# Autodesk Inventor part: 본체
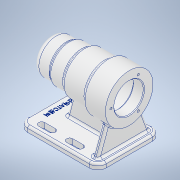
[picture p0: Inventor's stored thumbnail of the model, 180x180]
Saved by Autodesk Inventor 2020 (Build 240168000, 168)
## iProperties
Created: 2021-10
Part Number: 본체
Material: 알루미늄 6061
Document SubType Name: Modeling
Designer: user
Density: 2.7 g/cm^3
Appearance: 알루미늄 - 평지
Mass: 691.322 g
Surface Area: 698.567 cm^2
Volume: 256.045 cm^3
Author: user
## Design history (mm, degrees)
sketch "스케치1"
  geometry: L1 (0, 0)-(0, 27.861); L2 (0, 0)-(112, 0); L3 (112, 0)-(112, 34); L4 (112, 34)-(80, 34); L5 (80, 34)-(80, 30); L6 (80, 30)-(46, 30); L7 (46, 30)-(46, 27); L8 (46, 27)-(24, 27); L9 (24, 27)-(24, 25); L10 (24, 25)-(0, 25); L11 (0, 25)-(0, 0); 1 further point
  constraints: 22 end point, 8 perpendicular, 1 collinear, 1 horizontal, 1 vertical
  dimensions: "d0" = 112 distance between parallel lines of L3 L11; "d2" = 68 diameter of L4 L2; "d3" = 60 diameter of L6 L2; "d4" = 54 diameter of L8 L2; "d5" = 50 diameter of L10 L2; "d6" = 24 distance of L9.end L10.end; "d7" = 46 distance between parallel lines of L1 L7; "d8" = 80 distance between parallel lines of L1 L5
revolve "회전1" sketch "스케치1" stored, may be unused: angle "d9" = 90 deg
sketch "스케치2"
  geometry: C1 r 21 at (0, 0); 1 further point
  constraints: 1 centre point, 1 coincident
  dimensions: "d10" = 42 diameter of C1
extrude "돌출1" cut sketch "스케치2" distance "d11" = 15; taper "d12" = 0 deg
sketch "스케치3"
  geometry: C1 r 24 at (0, 0); 1 further point
  constraints: 1 centre point, 1 coincident
  dimensions: "d13" = 48 diameter of C1
extrude "돌출2" cut sketch "스케치3" distance "d14" = 54; taper "d15" = 0 deg
sketch "스케치4"
  geometry: C1 r 21 at (0, 0); 1 further point
  constraints: 1 centre point, 1 coincident
  dimensions: "d16" = 42 diameter of C1
extrude "돌출3" cut sketch "스케치4" distance "d17" = 12; taper "d18" = 0 deg
sketch "스케치5"
  geometry: C1 r 17.5 at (0, 0); 1 further point
  constraints: 1 centre point, 1 coincident
  dimensions: "d19" = 35 diameter of C1
extrude "돌출4" cut sketch "스케치5" distance "d20" = 18; taper "d21" = 0 deg
sketch "스케치6"
  geometry: C1 r 16 at (0, 0); 1 further point
  constraints: 1 centre point, 1 coincident
  dimensions: "d22" = 32 diameter of C1
extrude "돌출5" cut sketch "스케치6" distance "d23" = 4; taper "d24" = 0 deg
sketch "스케치7"
  geometry: C1 r 10.5 at (0, 0); 1 further point
  constraints: 1 centre point, 1 coincident
  dimensions: "d25" = 21 diameter of C1
extrude "돌출6" cut sketch "스케치7" distance "d26" = 3; taper "d27" = 0 deg
fillet "모깎기1" dims "d28" = 0.3
fillet "모깎기2" dims "d29" = 0.3
fillet "모깎기3" dims "d30" = 3
fillet "모깎기4" dims "d31" = 3
chamfer "모따기1" distance "d32" = 1; stored, may be unused: second distance "d33" = 2, angle "d34" = 45 deg
fillet "모깎기5" dims "d35" = 3
fillet "모깎기6" dims "d36" = 3
fillet "모깎기7" dims "d37" = 8
sketch "스케치11"
  geometry: L1 (0, 0)-(-26, 0); 1 further point
  constraints: 2 end point, 1 coincident, 1 horizontal
  dimensions: "d50" = 26 distance of L1.start L1.end
hole "구멍2" sketch "스케치11" at (-26, 0) diameter "d51" = 3.242; stored, may be unused: countersink angle "d55" = 90 deg, drill point angle "d57" = 118 deg; dims "d52" = 8, "d53" = 4, "d54" = 2, "d56" = 11
node "작업 평면2"
sketch "스케치12"
  geometry: L1 (0, 0)-(-56, 0); L2 (-112, -45)-(0, -45); L3 (0, -45)-(0, 45); L4 (0, 45)-(-112, 45); L5 (-112, 45)-(-112, -45); L6 (-112, -45)-(0, 45); L7 (0, -45)-(-112, 45)
  constraints: 14 end point, 2 horizontal, 2 midpoint, 2 parallel, 1 perpendicular
  dimensions: "d62" = 56 distance of L1.start L1.end; "d63" = 112 distance of L4.end L3.end; "d64" = 90 distance between parallel lines of L4 L2
extrude "돌출7" join sketch "스케치12" distance "d65" = 8; taper "d66" = 0 deg
fillet "모깎기8" dims "d67" = 12
fillet "모깎기9" dims "d68" = 3
sketch "스케치14"
  geometry: L1 (20, -33)-(35, -33); L2 (20, -37.5)-(35, -37.5); L3 (35, -28.5)-(20, -28.5); L4 (0, 33)-(0, -33) reference; L5 (60, -33)-(75, -33); L6 (60, -37.5)-(75, -37.5); L7 (75, -28.5)-(60, -28.5); A1 r 4.5 centre (20, -33) between (20, -28.5) and (20, -37.5); A2 r 4.5 centre (35, -33) between (35, -37.5) and (35, -28.5); A3 r 4.5 centre (60, -33) between (60, -28.5) and (60, -37.5); A4 r 4.5 centre (75, -33) between (75, -37.5) and (75, -28.5); 3 further points
  constraints: 16 end point, 8 point on circle, 8 tangent, 4 centre point, 2 horizontal, 2 midpoint, 2 parallel
  dimensions: "d69" = 15 distance of L1.start L1.end; "d70" = 20 distance from line of L4 L1.start; "d71" = 9 distance between parallel lines of L2 L3; "d72" = 33 vertical distance of point (0, 0) point (27.5, -33); "d75" = 15 distance of L5.end L5.start; "d76" = 25 distance of L5.start L1.end; "d77" = 9 distance between parallel lines of L6 L7; "d78" = 33 vertical distance of point (0, 0) point (67.5, -33)
extrude "돌출8" cut sketch "스케치14" extent not by distance; stored distance "d73" = 0; taper "d74" = 0 deg
sketch "스케치15"
  geometry: L1 (104, 37)-(96, 37); L2 (96, 37)-(96, -37); L3 (96, -37)-(104, -37); L4 (104, -37)-(104, 37); L5 (112, -33)-(112, 33) reference; L6 (12, -45)-(100, -45) reference; L7 (100, 45)-(12, 45) reference; L8 (27, 4)-(104, 4); L9 (104, 4)-(104, -4); L10 (104, -4)-(27, -4); L11 (27, -4)-(27, 4); 3 further points
  constraints: 16 end point, 4 parallel, 2 horizontal, 2 perpendicular
  dimensions: "d79" = 8 distance between parallel lines of L5 L4; "d80" = 8 distance between parallel lines of L4 L2; "d82" = 8 distance between parallel lines of L6 L3; "d83" = 8 distance between parallel lines of L7 L1; "d84" = 8 distance between parallel lines of L10 L8; "d85" = 8 distance between parallel lines of L5 L9; "d86" = 77 distance between parallel lines of L4 L11; "d87" = 4 distance from line of point (0, 0) L10
extrude "돌출9" join sketch "스케치15" stored distance "d88" = 10; taper "d89" = 0 deg
sketch "스케치16"
  geometry: L1 (-29, 0)-(37, 0) reference; L2 (-33.5, 0)-(-24.5, 0) reference; L3 (-38, 0)-(-29, 0) reference; L4 (-19.409, 37.342)-(-33, 0); L5 (-41, -3)-(-41, -8) reference; A1 r 34 centre (4, 62) between (8, 28.236) and (0, 28.236) reference; 1 further point
  constraints: 2 end point, 1 point on circle, 1 point on line
  dimensions: "d90" = 8 distance from line of L4.end L5; "d91" = 110 deg angle of L3 L4
feature "리브1" sketch "스케치16" dims "d92" = 1, "d93" = 8, "d94" = 0, "d95" = 0, "d96" = 1, "d97" = 1
feature "면 기울기1" dims angle "d98" = 15 deg
fillet "모깎기10" dims "d99" = 3
fillet "모깎기11" dims "d100" = 3
fillet "모깎기12" dims "d101" = 3
sketch "스케치17"
  geometry: L1 (0, 33)-(0, -33) reference; A1 r 4.5 centre (20, 33) between (20, 37.5) and (20, 28.5) reference; A2 r 4.5 centre (20, -33) between (20, -28.5) and (20, -37.5) reference; 2 further points
  constraints: 1 other
  dimensions: "d102" = 33 vertical distance of A1.centre point (12, 0); "d103" = 12 distance from line of L1 point (12, 0)
feature "엠보싱1" sketch "스케치17" dims "d0" = 112, "d2" = 68, "d3" = 60, "d4" = 54, "d5" = 50, "d6" = 24, "d7" = 46, "d8" = 80, "d11" = 15, "d104" = 0.5, "d105" = 0
node "솔리드1"
pattern_circular "원형 패턴1" dims angle "d59" = 360 deg
mirror "미러1"
mirror "미러2"
feature "A9D066F2-1C7D-4E18-AEED-F7BC21143FA4" dims "d51" = 3.242, "d52" = 8, "d53" = 4, "d54" = 2, "d55" = 90 deg, "d56" = 11, "d57" = 118 deg
